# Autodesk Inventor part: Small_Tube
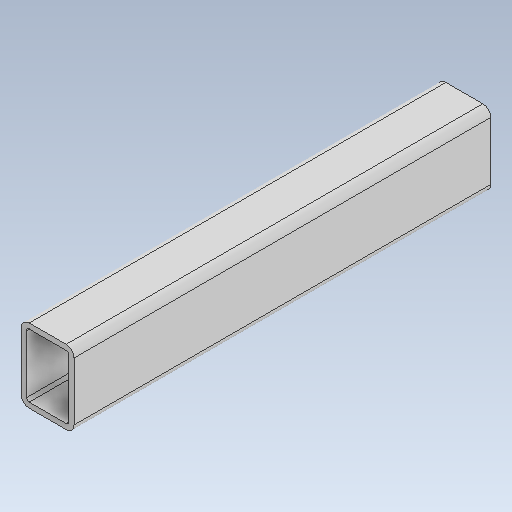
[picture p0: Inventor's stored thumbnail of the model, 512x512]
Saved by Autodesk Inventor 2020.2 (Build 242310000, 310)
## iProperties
Created: 2019-12
Part Number: Small_Tube
Material: Generic
Document SubType Name: Modeling
Designer: Patrick Everitt
Density: 1 g/cm^3
Appearance: Default
Description: 3.5x2.5 TUBE 19.75 Lg
Author: Patrick Everitt
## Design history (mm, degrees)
sketch "Sketch1"
  geometry: L1 (-30.162, -34.925)-(-30.162, 34.925); L2 (-20.637, 44.45)-(23.812, 44.45); L3 (33.337, 34.925)-(33.338, -34.925); L4 (23.813, -44.45)-(-20.637, -44.45); L5 (-23.813, 34.925)-(-23.813, -34.925); L6 (-20.638, -38.1)-(23.813, -38.1); L7 (26.988, -34.925)-(26.988, 34.925); L8 (23.813, 38.1)-(-20.638, 38.1); A1 r 9.525 centre (-20.637, 34.925) between (-20.637, 44.45) and (-30.162, 34.925); A2 r 9.525 centre (23.812, 34.925) between (33.337, 34.925) and (23.812, 44.45); A3 r 9.525 centre (-20.637, -34.925) between (-30.162, -34.925) and (-20.637, -44.45); A4 r 9.525 centre (23.813, -34.925) between (23.813, -44.45) and (33.338, -34.925); A5 r 3.175 centre (-20.637, -34.925) between (-23.813, -34.925) and (-20.638, -38.1); A6 r 3.175 centre (23.813, -34.925) between (23.813, -38.1) and (26.988, -34.925); A7 r 3.175 centre (23.812, 34.925) between (26.988, 34.925) and (23.813, 38.1); A8 r 3.175 centre (-20.637, 34.925) between (-20.638, 38.1) and (-23.813, 34.925); 4 further points
  constraints: 16 end point, 16 point on circle, 8 centre point, 6 tangent, 5 point on line, 4 perpendicular, 2 equal radius, 1 horizontal, 1 vertical, 7 other
  dimensions: "d2" = 63.5 distance of point (-30.162, 44.45) point (33.337, 44.45); "d3" = 90 deg angle of L1 L2 (derived); "d4" = 88.9 distance of point (33.337, 44.45) point (33.338, -44.45); "d5" = 90 deg angle of L2 L3 (derived); "d8" = 9.525 radius of A1 (derived); "d10" = 6.35 distance between parallel lines of L1 L5
extrude "Extrusion1" new body sketch "Sketch1" distance "d11" = 501.65; taper "d12" = 0 deg
body "Solid1"
